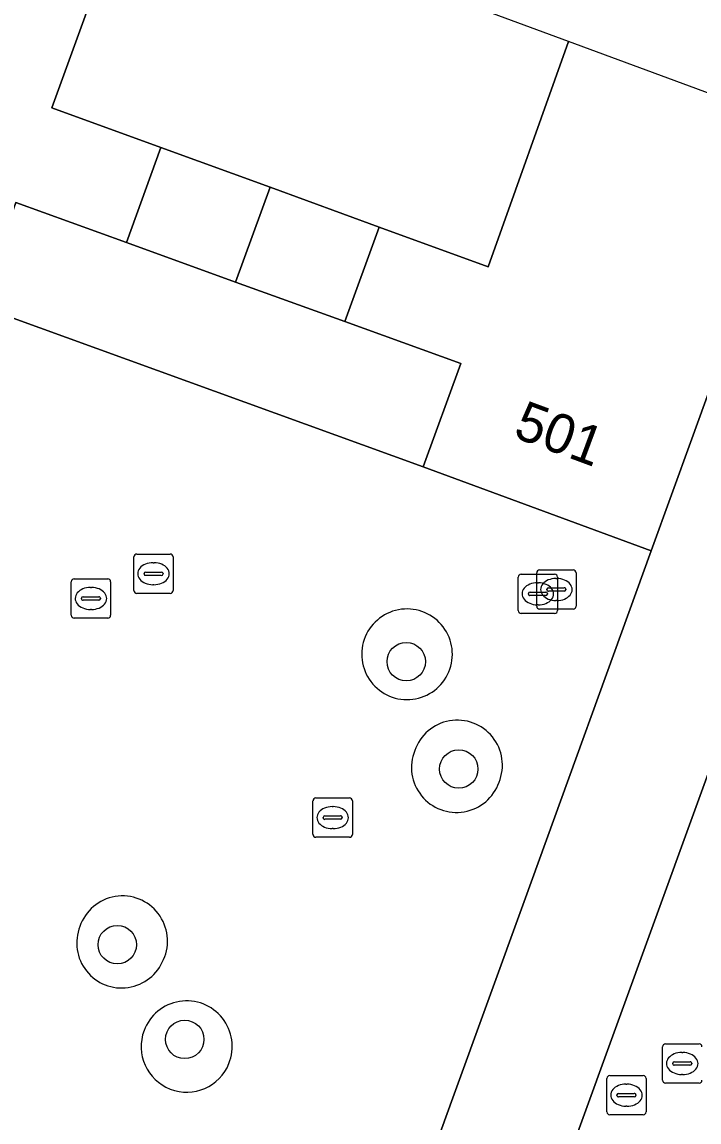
# Model space of a CAD drawing. Extents: x 155275 to 156265, y 382654 to 383635.
# Drawn here: x 155825.44 to 155842.67, y 383533.68 to 383561.67 of the extents above; entities that cross this region are included whole.
import ezdxf

# ---------------------------------------------------------------- set-up
doc = ezdxf.new("R2010")
doc.units = 0
for name, color, linetype in [('IMGEO_Boom', 7, 'Continuous'), ('IMGEO_Brandkraan', 7, 'Continuous'), ('IMGEO_Erf', 7, 'Continuous'), ('IMGEO_Groenvoorziening', 7, 'Continuous'), ('IMGEO_Kolk', 7, 'Continuous'), ('IMGEO_Pand', 7, 'Continuous'), ('IMGEO_Pand_nummerreeks', 7, 'Continuous'), ('IMGEO_Rijbaan_lokaal_gesloten', 7, 'Continuous'), ('IMGEO_Rijbaan_lokaal_open', 7, 'Continuous'), ('IMGEO_Rioolput', 7, 'Continuous'), ('IMGEO_Voetpad_open', 7, 'Continuous')]:
    doc.layers.add(name, color=color, linetype=linetype)

msp = doc.modelspace()

# ---------------------------------------------------------------- linework, layer by layer
at = {"layer": 'IMGEO_Boom'}
for centre in [(155835.216, 383545.396), (155836.553, 383542.664), (155827.864, 383538.194), (155829.581, 383535.785)]:
    msp.add_circle(centre, 0.489, dxfattribs=at)
at = {"layer": 'IMGEO_Brandkraan'}
for p, q in [((155838.536, 383546.804), (155838.536, 383547.656)), ((155838.611, 383547.73), (155839.463, 383547.73)), ((155839.537, 383547.656), (155839.537, 383546.804)), ((155838.065, 383546.695), (155838.065, 383547.547)), ((155838.14, 383547.621), (155838.992, 383547.621)), ((155838.553, 383547.401), (155838.578, 383547.401)), ((155839.024, 383547.51), (155839.049, 383547.51)), ((155839.066, 383547.547), (155839.066, 383546.695)), ((155838.324, 383547.115), (155838.324, 383547.127)), ((155838.762, 383547.078), (155838.364, 383547.078)), ((155838.367, 383547.164), (155838.765, 383547.164)), ((155838.795, 383547.224), (155838.795, 383547.236)), ((155838.808, 383547.127), (155838.808, 383547.115)), ((155839.233, 383547.187), (155838.835, 383547.187)), ((155838.838, 383547.273), (155839.236, 383547.273)), ((155839.279, 383547.236), (155839.279, 383547.224)), ((155838.576, 383546.841), (155838.551, 383546.841)), ((155839.047, 383546.95), (155839.022, 383546.95)), ((155838.992, 383546.621), (155838.14, 383546.621)), ((155839.463, 383546.73), (155838.611, 383546.73))]:
    msp.add_line(p, q, dxfattribs=at)
for points in [[(155838.536, 383546.804), (155838.536, 383547.656)], [(155838.611, 383547.73), (155839.463, 383547.73)], [(155839.537, 383547.656), (155839.537, 383546.804)], [(155838.065, 383546.695), (155838.065, 383547.547)], [(155838.14, 383547.621), (155838.992, 383547.621)], [(155839.066, 383547.547), (155839.066, 383546.695)], [(155838.992, 383546.621), (155838.14, 383546.621)], [(155839.463, 383546.73), (155838.611, 383546.73)]]:
    msp.add_lwpolyline(points, dxfattribs=at)
for centre, radius, start, end in [((155838.613, 383547.654), 0.0765, 91.552, 178.448), ((155838.613, 383547.654), 0.0765, 91.552, 178.448), ((155839.461, 383547.654), 0.0765, 1.552, 88.448), ((155839.461, 383547.654), 0.0765, 1.552, 88.448), ((155838.142, 383547.545), 0.0765, 91.552, 178.448), ((155838.142, 383547.545), 0.0765, 91.552, 178.448), ((155838.99, 383547.545), 0.0765, 1.552, 88.448), ((155838.99, 383547.545), 0.0765, 1.552, 88.448), ((155838.364, 383547.124), 0.0403, 85.8775, 175.7526), ((155838.361, 383547.114), 0.0366, 178.938, 274.7102), ((155838.765, 383547.121), 0.043, 264.8664, 352.4533), ((155838.769, 383547.126), 0.0386, 1.7309, 96.639), ((155838.835, 383547.233), 0.0403, 85.8775, 175.7526), ((155838.832, 383547.223), 0.0366, 178.938, 274.7102), ((155839.236, 383547.23), 0.043, 264.8664, 352.4533), ((155839.24, 383547.235), 0.0386, 1.7309, 96.639), ((155838.613, 383546.806), 0.0765, 181.552, 268.448), ((155838.613, 383546.806), 0.0765, 181.552, 268.448), ((155839.461, 383546.806), 0.0765, 271.552, 358.448), ((155839.461, 383546.806), 0.0765, 271.552, 358.448), ((155838.142, 383546.697), 0.0765, 181.552, 268.448), ((155838.142, 383546.697), 0.0765, 181.552, 268.448), ((155838.99, 383546.697), 0.0765, 271.552, 358.448), ((155838.99, 383546.697), 0.0765, 271.552, 358.448)]:
    msp.add_arc(centre, radius, start, end, dxfattribs=at)
for centre, major_axis, ratio, start_param, end_param in [((155838.552, 383547.121), (-0.387, 0.002), 0.722429, 4.712389, 7.853982), ((155838.577, 383547.121), (-0.39, 0.002), 0.717154, 1.570796, 4.712389), ((155839.023, 383547.23), (-0.387, 0.002), 0.722429, 4.712389, 7.853982), ((155839.048, 383547.23), (-0.39, 0.002), 0.717154, 1.570796, 4.712389)]:
    msp.add_ellipse(centre, major_axis=major_axis, ratio=ratio, start_param=start_param, end_param=end_param, dxfattribs=at)
at = {"layer": 'IMGEO_Erf'}
for points in [[(155839.346, 383561.171), (155828.292, 383565.25), (155826.2, 383559.485), (155828.976, 383558.474), (155831.751, 383557.463), (155834.527, 383556.452), (155837.302, 383555.441)], [(155830.873, 383555.054), (155828.096, 383556.058), (155825.283, 383557.075), (155824.346, 383554.447), (155835.646, 383550.348), (155836.604, 383552.982), (155833.651, 383554.049)]]:
    msp.add_lwpolyline(points, close=True, dxfattribs=at)
at = {"layer": 'IMGEO_Groenvoorziening'}
for centre, radius, start, end in [((155835.237, 383545.583), 1.153, 340.9243, 160.9646), ((155835.237, 383545.582), 1.153, 160.896, 340.9929), ((155836.517, 383542.761), 1.146, 337.7731, 161.1324), ((155836.496, 383542.705), 1.146, 158.092, 340.8135), ((155827.997, 383538.289), 1.146, 335.6801, 161.1448), ((155827.977, 383538.237), 1.144, 158.3823, 338.4426), ((155829.631, 383535.606), 1.159, 337.9933, 159.6337), ((155829.63, 383535.603), 1.159, 159.4718, 338.1552)]:
    msp.add_arc(centre, radius, start, end, dxfattribs=at)
at = {"layer": 'IMGEO_Kolk'}
for p, q in [((155832.844, 383541.001), (155832.844, 383541.853)), ((155832.919, 383541.927), (155833.771, 383541.927)), ((155833.845, 383541.853), (155833.845, 383541.001)), ((155833.146, 383541.47), (155833.544, 383541.47)), ((155833.332, 383541.707), (155833.357, 383541.707)), ((155833.103, 383541.421), (155833.103, 383541.433)), ((155833.541, 383541.384), (155833.143, 383541.384)), ((155833.587, 383541.433), (155833.587, 383541.421)), ((155833.771, 383540.927), (155832.919, 383540.927)), ((155833.355, 383541.147), (155833.33, 383541.147))]:
    msp.add_line(p, q, dxfattribs=at)
for points in [[(155832.844, 383541.001), (155832.844, 383541.853)], [(155832.919, 383541.927), (155833.771, 383541.927)], [(155833.845, 383541.853), (155833.845, 383541.001)], [(155833.771, 383540.927), (155832.919, 383540.927)]]:
    msp.add_lwpolyline(points, dxfattribs=at)
for centre, radius, start, end in [((155832.921, 383541.851), 0.0765, 91.552, 178.448), ((155832.921, 383541.851), 0.0765, 91.552, 178.448), ((155833.769, 383541.851), 0.0765, 1.552, 88.448), ((155833.769, 383541.851), 0.0765, 1.552, 88.448), ((155833.143, 383541.43), 0.0403, 85.8775, 175.7526), ((155833.548, 383541.432), 0.0386, 1.7309, 96.639), ((155833.14, 383541.42), 0.0366, 178.938, 274.7102), ((155833.544, 383541.427), 0.043, 264.8664, 352.4533), ((155832.921, 383541.003), 0.0765, 181.552, 268.448), ((155832.921, 383541.003), 0.0765, 181.552, 268.448), ((155833.769, 383541.003), 0.0765, 271.552, 358.448), ((155833.769, 383541.003), 0.0765, 271.552, 358.448)]:
    msp.add_arc(centre, radius, start, end, dxfattribs=at)
for centre, major_axis, ratio, start_param, end_param in [((155833.331, 383541.427), (-0.387, 0.002), 0.722429, 4.712389, 7.853982), ((155833.356, 383541.427), (-0.39, 0.002), 0.717154, 1.570796, 4.712389)]:
    msp.add_ellipse(centre, major_axis=major_axis, ratio=ratio, start_param=start_param, end_param=end_param, dxfattribs=at)
at = {"layer": 'IMGEO_Pand'}
for points in [[(155828.292, 383565.25), (155822.72, 383567.307), (155818.762, 383556.48), (155824.346, 383554.447), (155825.283, 383557.075), (155828.096, 383556.058), (155828.976, 383558.474), (155826.2, 383559.485)], [(155845.338, 383558.959), (155839.346, 383561.171), (155837.302, 383555.441), (155834.527, 383556.452), (155833.651, 383554.049), (155836.604, 383552.982), (155835.646, 383550.348), (155841.449, 383548.213), (155842.486, 383551.062)], [(155831.751, 383557.463), (155828.976, 383558.474), (155828.096, 383556.058), (155830.873, 383555.054)], [(155834.527, 383556.452), (155831.751, 383557.463), (155830.873, 383555.054), (155833.651, 383554.049)]]:
    msp.add_lwpolyline(points, close=True, dxfattribs=at)
at = {"layer": 'IMGEO_Rijbaan_lokaal_gesloten'}
msp.add_lwpolyline([(155853.664, 383555.887), (155848.443, 383557.813), (155839.582, 383533.423), (155873.88, 383520.938), (155953.014, 383492.142), (155990.266, 383437.67), (156009.401, 383409.628), (156027.144, 383383.663), (156049.518, 383350.943)], dxfattribs=at)
at = {"layer": 'IMGEO_Rijbaan_lokaal_open'}
msp.add_lwpolyline([(155816.49, 383537.046), (155815.693, 383534.703), (155820.057, 383533.119), (155828.406, 383530.071), (155834.138, 383528.04), (155834.269, 383528.401), (155834.855, 383530.018), (155835.25, 383531.107), (155836.406, 383534.298), (155838.216, 383539.294), (155841.449, 383548.213), (155835.646, 383550.348), (155824.346, 383554.447), (155818.762, 383556.48), (155813.199, 383558.505), (155801.897, 383562.616), (155796.316, 383564.637), (155790.759, 383566.649), (155785.087, 383568.733), (155781.636, 383569.994)], dxfattribs=at)
for centre, radius, start, end in [((155835.237, 383545.583), 1.153, 340.9243, 160.9646), ((155835.237, 383545.582), 1.153, 160.896, 340.9929), ((155836.517, 383542.761), 1.146, 337.7731, 161.1324), ((155836.496, 383542.705), 1.146, 158.092, 340.8135), ((155827.997, 383538.289), 1.146, 335.6801, 161.1448), ((155827.977, 383538.237), 1.144, 158.3823, 338.4426), ((155829.631, 383535.606), 1.159, 337.9933, 159.6337), ((155829.63, 383535.603), 1.159, 159.4718, 338.1552)]:
    msp.add_arc(centre, radius, start, end, dxfattribs=at)
at = {"layer": 'IMGEO_Rioolput'}
for p, q in [((155828.286, 383547.207), (155828.286, 383548.059)), ((155828.361, 383548.133), (155829.213, 383548.133)), ((155828.774, 383547.913), (155828.799, 383547.913)), ((155829.287, 383548.059), (155829.287, 383547.207)), ((155828.545, 383547.627), (155828.545, 383547.639)), ((155828.588, 383547.676), (155828.986, 383547.676)), ((155829.029, 383547.639), (155829.029, 383547.627)), ((155826.694, 383546.577), (155826.694, 383547.429)), ((155826.769, 383547.503), (155827.621, 383547.503)), ((155827.695, 383547.429), (155827.695, 383546.577)), ((155828.983, 383547.59), (155828.585, 383547.59)), ((155828.797, 383547.353), (155828.772, 383547.353)), ((155827.182, 383547.283), (155827.207, 383547.283)), ((155829.213, 383547.133), (155828.361, 383547.133)), ((155826.953, 383546.997), (155826.953, 383547.009)), ((155827.391, 383546.96), (155826.993, 383546.96)), ((155826.996, 383547.046), (155827.394, 383547.046)), ((155827.437, 383547.009), (155827.437, 383546.997)), ((155827.205, 383546.723), (155827.18, 383546.723)), ((155827.621, 383546.503), (155826.769, 383546.503)), ((155841.738, 383534.746), (155841.738, 383535.598)), ((155841.813, 383535.672), (155842.665, 383535.672)), ((155842.226, 383535.452), (155842.251, 383535.452)), ((155841.997, 383535.166), (155841.997, 383535.178)), ((155842.435, 383535.129), (155842.037, 383535.129)), ((155842.04, 383535.215), (155842.438, 383535.215)), ((155842.481, 383535.178), (155842.481, 383535.166)), ((155840.319, 383533.94), (155840.319, 383534.792)), ((155840.394, 383534.866), (155841.246, 383534.866)), ((155841.32, 383534.792), (155841.32, 383533.94)), ((155842.249, 383534.892), (155842.224, 383534.892)), ((155840.807, 383534.646), (155840.832, 383534.646)), ((155842.665, 383534.672), (155841.813, 383534.672)), ((155840.578, 383534.36), (155840.578, 383534.372)), ((155841.016, 383534.323), (155840.618, 383534.323)), ((155840.621, 383534.409), (155841.019, 383534.409)), ((155841.062, 383534.372), (155841.062, 383534.36)), ((155840.83, 383534.086), (155840.805, 383534.086)), ((155841.246, 383533.866), (155840.394, 383533.866))]:
    msp.add_line(p, q, dxfattribs=at)
for points in [[(155828.286, 383547.207), (155828.286, 383548.059)], [(155828.361, 383548.133), (155829.213, 383548.133)], [(155829.287, 383548.059), (155829.287, 383547.207)], [(155826.694, 383546.577), (155826.694, 383547.429)], [(155826.769, 383547.503), (155827.621, 383547.503)], [(155827.695, 383547.429), (155827.695, 383546.577)], [(155829.213, 383547.133), (155828.361, 383547.133)], [(155827.621, 383546.503), (155826.769, 383546.503)], [(155841.738, 383534.746), (155841.738, 383535.598)], [(155841.813, 383535.672), (155842.665, 383535.672)], [(155840.319, 383533.94), (155840.319, 383534.792)], [(155840.394, 383534.866), (155841.246, 383534.866)], [(155841.32, 383534.792), (155841.32, 383533.94)], [(155842.665, 383534.672), (155841.813, 383534.672)], [(155841.246, 383533.866), (155840.394, 383533.866)]]:
    msp.add_lwpolyline(points, dxfattribs=at)
for centre, radius, start, end in [((155828.363, 383548.057), 0.0765, 91.552, 178.448), ((155828.363, 383548.057), 0.0765, 91.552, 178.448), ((155829.211, 383548.057), 0.0765, 1.552, 88.448), ((155829.211, 383548.057), 0.0765, 1.552, 88.448), ((155828.585, 383547.636), 0.0403, 85.8775, 175.7526), ((155828.582, 383547.626), 0.0366, 178.938, 274.7102), ((155828.986, 383547.633), 0.043, 264.8664, 352.4533), ((155828.99, 383547.638), 0.0386, 1.7309, 96.639), ((155826.771, 383547.427), 0.0765, 91.552, 178.448), ((155826.771, 383547.427), 0.0765, 91.552, 178.448), ((155827.619, 383547.427), 0.0765, 1.552, 88.448), ((155827.619, 383547.427), 0.0765, 1.552, 88.448), ((155828.363, 383547.209), 0.0765, 181.552, 268.448), ((155828.363, 383547.209), 0.0765, 181.552, 268.448), ((155829.211, 383547.209), 0.0765, 271.552, 358.448), ((155829.211, 383547.209), 0.0765, 271.552, 358.448), ((155826.993, 383547.006), 0.0403, 85.8775, 175.7526), ((155826.99, 383546.996), 0.0366, 178.938, 274.7102), ((155827.394, 383547.003), 0.043, 264.8664, 352.4533), ((155827.398, 383547.008), 0.0386, 1.7309, 96.639), ((155826.771, 383546.579), 0.0765, 181.552, 268.448), ((155826.771, 383546.579), 0.0765, 181.552, 268.448), ((155827.619, 383546.579), 0.0765, 271.552, 358.448), ((155827.619, 383546.579), 0.0765, 271.552, 358.448), ((155841.815, 383535.596), 0.0765, 91.552, 178.448), ((155841.815, 383535.596), 0.0765, 91.552, 178.448), ((155842.663, 383535.596), 0.0765, 1.552, 88.448), ((155842.663, 383535.596), 0.0765, 1.552, 88.448), ((155842.037, 383535.175), 0.0403, 85.8775, 175.7526), ((155842.034, 383535.165), 0.0366, 178.938, 274.7102), ((155842.438, 383535.172), 0.043, 264.8664, 352.4533), ((155842.442, 383535.177), 0.0386, 1.7309, 96.639), ((155840.396, 383534.79), 0.0765, 91.552, 178.448), ((155840.396, 383534.79), 0.0765, 91.552, 178.448), ((155841.244, 383534.79), 0.0765, 1.552, 88.448), ((155841.244, 383534.79), 0.0765, 1.552, 88.448), ((155841.815, 383534.748), 0.0765, 181.552, 268.448), ((155841.815, 383534.748), 0.0765, 181.552, 268.448), ((155842.663, 383534.748), 0.0765, 271.552, 358.448), ((155842.663, 383534.748), 0.0765, 271.552, 358.448), ((155840.618, 383534.369), 0.0403, 85.8775, 175.7526), ((155840.615, 383534.359), 0.0366, 178.938, 274.7102), ((155841.019, 383534.366), 0.043, 264.8664, 352.4533), ((155841.023, 383534.371), 0.0386, 1.7309, 96.639), ((155840.396, 383533.942), 0.0765, 181.552, 268.448), ((155840.396, 383533.942), 0.0765, 181.552, 268.448), ((155841.244, 383533.942), 0.0765, 271.552, 358.448), ((155841.244, 383533.942), 0.0765, 271.552, 358.448)]:
    msp.add_arc(centre, radius, start, end, dxfattribs=at)
for centre, major_axis, ratio, start_param, end_param in [((155828.773, 383547.633), (-0.387, 0.002), 0.722429, 4.712389, 7.853982), ((155828.798, 383547.633), (-0.39, 0.002), 0.717154, 1.570796, 4.712389), ((155827.181, 383547.003), (-0.387, 0.002), 0.722429, 4.712389, 7.853982), ((155827.206, 383547.003), (-0.39, 0.002), 0.717154, 1.570796, 4.712389), ((155842.225, 383535.172), (-0.387, 0.002), 0.722429, 4.712389, 7.853982), ((155842.25, 383535.172), (-0.39, 0.002), 0.717154, 1.570796, 4.712389), ((155840.806, 383534.366), (-0.387, 0.002), 0.722429, 4.712389, 7.853982), ((155840.831, 383534.366), (-0.39, 0.002), 0.717154, 1.570796, 4.712389)]:
    msp.add_ellipse(centre, major_axis=major_axis, ratio=ratio, start_param=start_param, end_param=end_param, dxfattribs=at)
at = {"layer": 'IMGEO_Voetpad_open'}
for points in [[(155845.338, 383558.959), (155842.486, 383551.062), (155841.449, 383548.213), (155838.216, 383539.294), (155836.406, 383534.298), (155835.25, 383531.107), (155856.569, 383523.296)], [(156049.518, 383350.943), (156027.144, 383383.663), (156009.401, 383409.628), (155990.266, 383437.67), (155953.014, 383492.142), (155873.88, 383520.938), (155839.582, 383533.423), (155848.443, 383557.813), (155845.338, 383558.959)]]:
    msp.add_lwpolyline(points, dxfattribs=at)

# ---------------------------------------------------------------- texts
at = {"layer": 'IMGEO_Pand_nummerreeks'}
msp.add_text('501', height=1, rotation=339.6027, dxfattribs=at).set_placement((155837.905, 383551.12))

doc.saveas('drawing.dxf')
